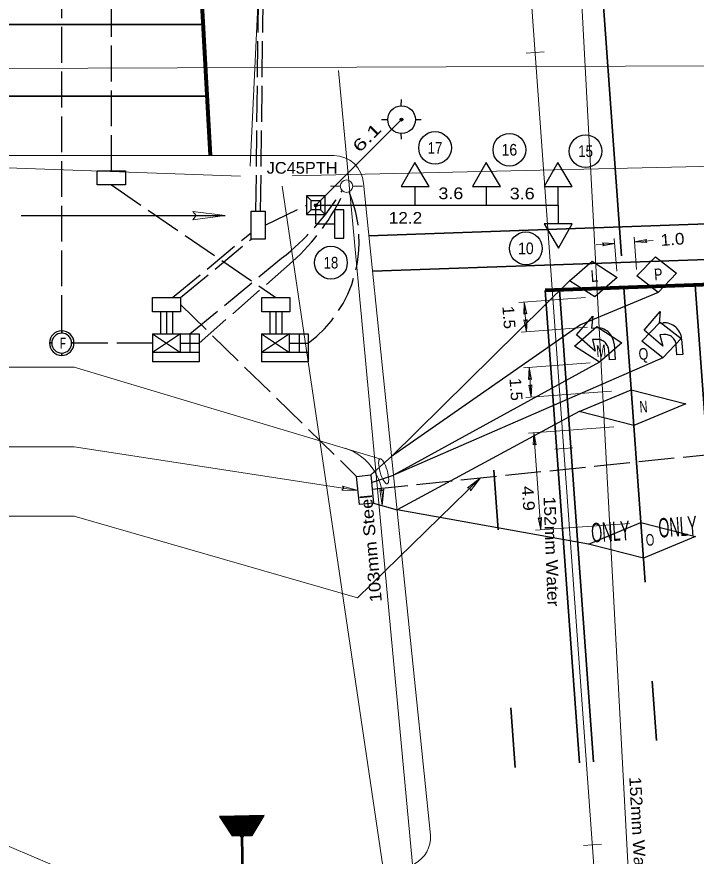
# Model space of a CAD drawing. Extents: x 168203 to 169864, y 223196 to 223870.
# Drawn here: x 168325.25 to 168359.48, y 223583.39 to 223625.66 of the extents above; entities that cross this region are included whole.
import ezdxf
from ezdxf.enums import TextEntityAlignment as Align

# ---------------------------------------------------------------- set-up
doc = ezdxf.new("R2010")
doc.units = 0
doc.header["$LTSCALE"] = 0.3
doc.header["$PDMODE"] = 32
doc.header["$PDSIZE"] = 0.15
doc.linetypes.add('LONG_DASH_SHORT_DASH', pattern=[9.9, 6, -1.2, 1.5, -1.2])
doc.linetypes.add('LONG_DASHED', pattern=[7.5, 6, -1.5])
for name, color, linetype, lineweight in [('1', 7, 'Continuous', 13), ('10', 7, 'Continuous', 13), ('23', 7, 'Continuous', 25), ('32', 7, 'Continuous', 25), ('36', 7, 'Continuous', 35), ('4', 7, 'Continuous', 25), ('6', 7, 'Continuous', 25), ('8', 7, 'Continuous', 25)]:
    doc.layers.add(name, color=color, linetype=linetype, lineweight=lineweight)

msp = doc.modelspace()

# ---------------------------------------------------------------- linework, layer by layer
at = {"layer": '1'}
for p, q in [((168355.9956, 223559.8648), (168350.6186, 223634.2675)), ((168350.9207, 223623.8346), (168351.8184, 223623.8995)), ((168298.0344, 223618.6676), (168341.2267, 223618.6675)), ((168341.5495, 223617.1291), (168341.0495, 223617.1291)), ((168342.1745, 223617.1291), (168342.6745, 223617.1291)), ((168342.7229, 223617.2756), (168346.0972, 223584.4572)), ((168352.3629, 223603.8867), (168353.2606, 223603.9516)), ((168280.5516, 223602.5453), (168328.4093, 223582.3863)), ((168353.8048, 223583.9354), (168354.7025, 223584.0002))]:
    msp.add_line(p, q, dxfattribs=at)
msp.add_circle((168341.862, 223617.1291), 0.3125, dxfattribs=at)
for centre, start, end in [((168341.2267, 223617.1675), 4.13349, 90.00005), ((168344.6012, 223584.3492), 297.10142, 4.13349)]:
    msp.add_arc(centre, 1.5, start, end, dxfattribs=at)
at = {"layer": '10', "lineweight": 25}
msp.add_line((168325.472, 223615.6542), (168335.7557, 223615.6542), dxfattribs=at)
at = {"layer": '10'}
for p, q in [((168328.1441, 223608.0135), (168297.9363, 223608.0135)), ((168343.5506, 223603.4058), (168328.1441, 223608.0135)), ((168328.1441, 223604.0135), (168297.9363, 223604.0135)), ((168342.4448, 223601.8094), (168328.1441, 223604.0135)), ((168328.1441, 223600.5135), (168297.9363, 223600.5135))]:
    msp.add_line(p, q, dxfattribs=at)
for points in [[(168334.1291, 223615.853), (168335.7557, 223615.6542), (168334.1291, 223615.4374), (168334.2919, 223615.6542)], [(168347.9575, 223601.9456), (168348.6085, 223602.4431), (168348.1028, 223601.797), (168348.0852, 223601.9314)], [(168341.6561, 223602.0315), (168342.4448, 223601.8094), (168341.6245, 223601.8262), (168341.7214, 223601.9209)], [(168343.744, 223601.8665), (168343.659, 223601.0515), (168343.5363, 223601.8628), (168343.6461, 223601.7833)]]:
    msp.add_lwpolyline(points, close=True, dxfattribs=at)
msp.add_lwpolyline([(168348.6085, 223602.4431), (168342.4242, 223596.3958), (168328.1441, 223600.5135)], dxfattribs=at)
msp.add_arc((168340.9894, 223601.3663), 2.6881, 353.27499, 72.67074, dxfattribs=at)
msp.add_ellipse((168343.7344, 223602.7761), major_axis=(-0.1838, 0.6297), ratio=0.276966, dxfattribs=at)
at = {"layer": '23', "lineweight": 13}
for p, q in [((168357.586, 223554.132), (168349.5897, 223703.4835)), ((168340.1403, 223682.8465), (168337.0072, 223618.1402)), ((168298.0362, 223622.959), (168427.4519, 223623.4301)), ((168347.1263, 223562.1814), (168341.4609, 223622.959)), ((168233.3078, 223621.2838), (168336.515, 223617.6326)), ((168339.1201, 223617.6451), (168427.4519, 223619.7026)), ((168348.0491, 223553.4435), (168338.6279, 223617.1375))]:
    msp.add_line(p, q, dxfattribs=at)
at = {"layer": '23'}
for p, q in [((168335.4735, 223585.375), (168337.6918, 223585.4203)), ((168335.4897, 223585.3503), (168337.6767, 223585.395)), ((168335.5057, 223585.3255), (168337.6615, 223585.3697)), ((168335.5219, 223585.3009), (168337.6465, 223585.3444)), ((168335.538, 223585.2762), (168337.6313, 223585.3191)), ((168335.5542, 223585.2515), (168337.6162, 223585.2937)), ((168335.5703, 223585.2269), (168337.6011, 223585.2684)), ((168335.5864, 223585.2022), (168337.586, 223585.2432)), ((168335.6025, 223585.1775), (168337.5709, 223585.2179)), ((168335.6188, 223585.1529), (168337.5558, 223585.1925)), ((168335.6348, 223585.1282), (168337.5407, 223585.1672)), ((168335.6509, 223585.1035), (168337.5256, 223585.1419)), ((168335.6671, 223585.0788), (168337.5104, 223585.1166)), ((168335.6832, 223585.0541), (168337.4953, 223585.0912)), ((168335.6994, 223585.0294), (168337.4802, 223585.0659)), ((168335.7155, 223585.0048), (168337.4651, 223585.0406)), ((168335.7316, 223584.9801), (168337.45, 223585.0153)), ((168335.7478, 223584.9554), (168337.435, 223584.99)), ((168335.7639, 223584.9308), (168337.4198, 223584.9646)), ((168335.78, 223584.9061), (168337.4047, 223584.9394)), ((168335.7961, 223584.8814), (168337.3895, 223584.9141)), ((168335.8123, 223584.8568), (168337.3745, 223584.8888)), ((168335.8284, 223584.8321), (168337.3593, 223584.8634)), ((168335.8446, 223584.8074), (168337.3442, 223584.8381)), ((168335.8606, 223584.7827), (168337.3291, 223584.8128)), ((168335.8769, 223584.758), (168337.3141, 223584.7875)), ((168335.893, 223584.7334), (168337.2989, 223584.7622)), ((168335.9091, 223584.7087), (168337.2838, 223584.7368)), ((168335.9252, 223584.684), (168337.2687, 223584.7115)), ((168335.9413, 223584.6594), (168337.2536, 223584.6862)), ((168335.9575, 223584.6347), (168337.2384, 223584.6609)), ((168335.9736, 223584.61), (168337.2233, 223584.6355)), ((168335.9897, 223584.5853), (168337.2083, 223584.6103)), ((168336.0059, 223584.5606), (168337.1932, 223584.585)), ((168336.0221, 223584.5359), (168337.178, 223584.5597)), ((168336.0381, 223584.5113), (168337.163, 223584.5343)), ((168336.0543, 223584.4866), (168337.1479, 223584.509)), ((168336.0705, 223584.4619), (168337.1327, 223584.4837)), ((168336.0866, 223584.4373), (168337.1175, 223584.4584))]:
    msp.add_line(p, q, dxfattribs=at)
at = {"layer": '23', "lineweight": 53}
msp.add_line((168336.8416, 223572.7261), (168336.6026, 223584.4228), dxfattribs=at)
at = {"layer": '23'}
msp.add_lwpolyline([(168336.1027, 223584.4126), (168337.1025, 223584.4331), (168337.7069, 223585.4457), (168335.4573, 223585.3996)], close=True, dxfattribs=at)
msp.add_point((168336.6026, 223584.4228), dxfattribs=at)
at = {"layer": '32'}
for p, q in [((168340.3237, 223616.1675), (168344.6371, 223620.4809)), ((168345.3237, 223616.1675), (168345.3237, 223617.1073)), ((168348.9237, 223616.1675), (168348.9237, 223617.1073)), ((168340.3237, 223615.2277), (168340.3237, 223616.1675)), ((168352.5237, 223616.1675), (168352.5237, 223615.2277)), ((168340.3237, 223615.2277), (168341.2635, 223615.2277))]:
    msp.add_line(p, q, dxfattribs=at)
for points in [[(168345.3056, 223618.3271), (168344.6189, 223617.1073), (168345.3237, 223617.1073), (168346.0285, 223617.1073)], [(168348.9056, 223618.3271), (168348.2189, 223617.1073), (168348.9237, 223617.1073), (168349.6285, 223617.1073)], [(168352.5056, 223618.3271), (168351.8189, 223617.1073), (168352.5237, 223617.1073), (168353.2285, 223617.1073)], [(168341.7333, 223614.5138), (168341.7333, 223615.9325), (168341.2635, 223615.9325), (168341.2635, 223614.5138)], [(168352.5418, 223614.0079), (168353.2285, 223615.2277), (168352.5237, 223615.2277), (168351.8189, 223615.2277)]]:
    msp.add_lwpolyline(points, close=True, dxfattribs=at)
msp.add_lwpolyline([(168340.3237, 223616.1675), (168352.5237, 223616.1675), (168352.5237, 223617.1073)], dxfattribs=at)
for centre in [(168346.3229, 223619.0571), (168350.0688, 223618.964), (168353.9078, 223618.8942), (168350.8998, 223614.0005), (168341.0797, 223613.279)]:
    msp.add_circle(centre, 0.8236, dxfattribs=at)
at = {"layer": '36', "lineweight": 80}
for p, q in [((168335.0149, 223618.6671), (168334.1789, 223633.9633)), ((168374.8667, 223612.7316), (168351.8768, 223611.872))]:
    msp.add_line(p, q, dxfattribs=at)
at = {"layer": '36'}
for p, q in [((168355.7208, 223613.6203), (168354.7732, 223626.7317)), ((168319.4575, 223625.267), (168334.6542, 223625.267)), ((168298.0351, 223621.6671), (168334.851, 223621.667)), ((168374.0279, 223615.7265), (168342.9941, 223614.6383)), ((168375.9373, 223613.9924), (168343.1786, 223612.8438)), ((168353.5949, 223588.0975), (168351.8768, 223611.872)), ((168354.3131, 223588.1493), (168352.5967, 223611.8989)), ((168356.9077, 223597.1964), (168355.8364, 223612.0201)), ((168361.075, 223589.4767), (168359.4361, 223612.1546)), ((168349.4984, 223599.8327), (168349.2822, 223602.8249)), ((168357.4843, 223589.2172), (168357.268, 223592.2094)), ((168350.3634, 223587.8639), (168350.1472, 223590.8561))]:
    msp.add_line(p, q, dxfattribs=at)
at = {"layer": '36', "linetype": 'LONG_DASH_SHORT_DASH', "lineweight": 25}
for points in [[(168354.4494, 223609.4175), (168354.2548, 223609.4034), (168354.3942, 223608.8268), (168353.4554, 223609.639), (168354.2676, 223610.5778), (168354.2126, 223609.9871), (168354.4072, 223610.0012)], [(168357.8515, 223609.6633), (168357.6569, 223609.6492), (168357.7963, 223609.0726), (168356.8575, 223609.8848), (168357.6697, 223610.8236), (168357.6147, 223610.2329), (168357.8093, 223610.247)], [(168358.7481, 223609.4347), (168358.8043, 223608.6565), (168358.5125, 223608.6354), (168358.4773, 223609.1218)], [(168355.346, 223609.1889), (168355.4022, 223608.4107), (168355.1104, 223608.3896), (168355.0752, 223608.876)]]:
    msp.add_lwpolyline(points, dxfattribs=at)
for centre, radius in [((168357.8725, 223609.3714), 0.8778), ((168354.4704, 223609.1256), 0.8778), ((168354.4915, 223608.8338), 0.5852), ((168357.8936, 223609.0796), 0.5852)]:
    msp.add_arc(centre, radius, 4.13419, 94.13419, dxfattribs=at)
at = {"layer": '4'}
for p, q in [((168339.8448, 223616.6374), (168340.0798, 223616.4024)), ((168340.7846, 223616.6374), (168340.5496, 223616.4024)), ((168339.8448, 223615.6976), (168340.0798, 223615.9326)), ((168340.7846, 223615.6976), (168340.5496, 223615.9326))]:
    msp.add_line(p, q, dxfattribs=at)
for points in [[(168339.8448, 223616.6374), (168339.8448, 223615.6976), (168340.7846, 223615.6976), (168340.7846, 223616.6374)], [(168340.0798, 223616.4024), (168340.5496, 223616.4024), (168340.5496, 223615.9326), (168340.0798, 223615.9326)]]:
    msp.add_lwpolyline(points, close=True, dxfattribs=at)
msp.add_point((168340.3237, 223616.1675), dxfattribs=at)
at = {"layer": '6', "linetype": 'LONG_DASHED'}
for p, q in [((168337.299, 223615.8769), (168337.8409, 223661.006)), ((168337.5361, 223615.8769), (168338.0771, 223660.9241)), ((168327.5151, 223609.8472), (168327.5152, 223654.5336)), ((168330.0164, 223617.906), (168330.0165, 223654.3633)), ((168330.0164, 223617.1922), (168338.2986, 223611.5244)), ((168337.7676, 223615.1676), (168339.8448, 223616.1675)), ((168333.1047, 223611.5244), (168337.0538, 223614.7891)), ((168333.505, 223611.5244), (168337.0538, 223614.4582)), ((168333.9743, 223609.6986), (168338.5949, 223613.5)), ((168334.4352, 223609.2287), (168339.1426, 223613.3344)), ((168333.505, 223611.1675), (168342.3722, 223602.515)), ((168332.5, 223610.8106), (168332.5, 223609.6986)), ((168332.7956, 223610.8106), (168332.7956, 223609.6986)), ((168333.0994, 223610.8106), (168333.0994, 223609.6986)), ((168338.003, 223610.8106), (168338.003, 223609.6986)), ((168338.2986, 223610.8106), (168338.2986, 223609.6986)), ((168338.6024, 223610.8106), (168338.6024, 223609.6986)), ((168332.0858, 223609.2287), (168328.1336, 223609.2287)), ((168343.1548, 223601.8824), (168372.8225, 223604.9326)), ((168343.0823, 223602.588), (168344.137, 223603.5217)), ((168343.1206, 223602.2151), (168344.2347, 223602.5721)), ((168343.2274, 223601.1767), (168344.4135, 223600.8327))]:
    msp.add_line(p, q, dxfattribs=at)
at = {"layer": '6', "lineweight": 13}
for p, q in [((168355.4744, 223612.8592), (168355.3562, 223614.4939)), ((168356.4725, 223612.9314), (168356.3543, 223614.5661)), ((168356.3721, 223614.3203), (168357.3101, 223614.3881)), ((168354.436, 223614.1804), (168355.374, 223614.2482)), ((168350.5485, 223611.2783), (168353.8961, 223611.5202)), ((168350.9293, 223609.8018), (168350.8212, 223611.2979)), ((168350.6566, 223609.7822), (168354.0042, 223610.0241)), ((168350.7863, 223607.9868), (168354.1339, 223608.2287)), ((168351.1671, 223606.5103), (168351.059, 223608.0065)), ((168350.8944, 223606.4906), (168355.2071, 223606.8023)), ((168351.0242, 223604.6952), (168355.3369, 223605.0069)), ((168351.6501, 223599.8276), (168351.2969, 223604.7149)), ((168351.3774, 223599.8079), (168356.1187, 223600.1506))]:
    msp.add_line(p, q, dxfattribs=at)
at = {"layer": '6'}
for p, q in [((168353.1038, 223612.3653), (168344.137, 223603.5217)), ((168327.5151, 223609.8488), (168327.5151, 223609.7313)), ((168327.5151, 223609.7313), (168327.5151, 223609.8488)), ((168327.5151, 223609.7313), (168327.5151, 223609.8488)), ((168327.5151, 223609.7313), (168327.5151, 223609.8488)), ((168332.0858, 223609.6986), (168333.4954, 223608.7588)), ((168333.4954, 223609.6986), (168332.0858, 223608.7588)), ((168332.0858, 223609.6986), (168334.4352, 223609.6986)), ((168332.0858, 223609.6986), (168332.0858, 223608.7588)), ((168333.4954, 223608.7588), (168333.4954, 223609.6986)), ((168333.9743, 223609.6986), (168333.9743, 223608.7588)), ((168334.4352, 223609.6986), (168334.4352, 223608.7588)), ((168337.5888, 223609.6986), (168338.9984, 223608.7588)), ((168338.9984, 223609.6986), (168337.5888, 223608.7588)), ((168337.5888, 223609.6986), (168339.9382, 223609.6986)), ((168337.5888, 223609.6986), (168337.5888, 223608.7588)), ((168338.9984, 223608.7588), (168338.9984, 223609.6986)), ((168339.4773, 223609.6986), (168339.4773, 223608.7588)), ((168339.9382, 223609.6986), (168339.9382, 223608.7588)), ((168327.0181, 223609.2343), (168326.8916, 223609.2343)), ((168326.8916, 223609.2343), (168327.0181, 223609.2343)), ((168326.8916, 223609.2343), (168327.0181, 223609.2343)), ((168327.0181, 223609.2343), (168326.8916, 223609.2343)), ((168328.0121, 223609.2343), (168328.1386, 223609.2343)), ((168328.1386, 223609.2343), (168328.0121, 223609.2343)), ((168328.0121, 223609.2343), (168328.1386, 223609.2343)), ((168328.1386, 223609.2343), (168328.0121, 223609.2343)), ((168333.4954, 223609.2287), (168334.4352, 223609.2287)), ((168338.9984, 223609.2287), (168339.9382, 223609.2287)), ((168327.5151, 223608.6108), (168327.5151, 223608.7283)), ((168327.5151, 223608.7283), (168327.5151, 223608.6108)), ((168327.5151, 223608.6108), (168327.5151, 223608.7283)), ((168327.5151, 223608.6108), (168327.5151, 223608.7283)), ((168334.4352, 223608.7588), (168332.0858, 223608.7588)), ((168332.0858, 223608.7588), (168332.0858, 223608.2889)), ((168334.4352, 223608.7588), (168334.4352, 223608.2889)), ((168339.9382, 223608.7588), (168337.5888, 223608.7588)), ((168337.5888, 223608.7588), (168337.5888, 223608.2889)), ((168339.9382, 223608.7588), (168339.9382, 223608.2889)), ((168357.7959, 223608.4933), (168344.2347, 223602.5721)), ((168334.4352, 223608.2889), (168332.0858, 223608.2889)), ((168339.9382, 223608.2889), (168337.5888, 223608.2889)), ((168354.6035, 223608.2625), (168344.2347, 223602.5721)), ((168353.5796, 223605.7823), (168344.4135, 223600.8327)), ((168354.0626, 223599.0996), (168344.4135, 223600.8327))]:
    msp.add_line(p, q, dxfattribs=at)
for points in [[(168329.3071, 223617.1922), (168329.3071, 223617.906), (168330.7258, 223617.906), (168330.7258, 223617.1922)], [(168337.7676, 223614.4582), (168337.0538, 223614.4582), (168337.0538, 223615.8769), (168337.7676, 223615.8769)], [(168356.4957, 223612.6104), (168357.4282, 223613.5802), (168358.4904, 223612.7546), (168357.558, 223611.7848)], [(168354.2359, 223613.3495), (168355.4976, 223612.5383), (168354.3656, 223611.5541), (168353.1038, 223612.3653)], [(168332.0863, 223610.8106), (168332.0863, 223611.5244), (168333.505, 223611.5244), (168333.505, 223610.8106)], [(168337.5893, 223610.8106), (168337.5893, 223611.5244), (168339.008, 223611.5244), (168339.008, 223610.8106)], [(168356.7336, 223609.3189), (168357.6661, 223610.2887), (168358.7283, 223609.4631), (168357.7959, 223608.4933)], [(168354.4738, 223610.0579), (168355.7355, 223609.2467), (168354.6035, 223608.2625), (168353.3417, 223609.0737)], [(168353.5796, 223605.7823), (168356.208, 223606.8746), (168358.9662, 223606.1716), (168356.3378, 223605.0792)], [(168342.3722, 223602.515), (168343.0823, 223602.588), (168343.2274, 223601.1767), (168342.5173, 223601.1037)], [(168354.0626, 223599.0996), (168356.691, 223600.1919), (168359.4492, 223599.4889), (168356.8208, 223598.3965)]]:
    msp.add_lwpolyline(points, close=True, dxfattribs=at)
at = {"layer": '6', "lineweight": 13}
for points in [[(168356.9858, 223614.2899), (168356.3721, 223614.3203), (168356.9746, 223614.4453), (168356.9196, 223614.3598)], [(168354.7603, 223614.2786), (168355.374, 223614.2482), (168354.7715, 223614.1232), (168354.8265, 223614.2087)], [(168350.7908, 223610.6842), (168350.8212, 223611.2979), (168350.9462, 223610.6954), (168350.8607, 223610.7504)], [(168350.9597, 223610.4155), (168350.9293, 223609.8018), (168350.8043, 223610.4043), (168350.8898, 223610.3493)], [(168351.0286, 223607.3928), (168351.059, 223608.0065), (168351.184, 223607.404), (168351.0985, 223607.459)], [(168351.1975, 223607.124), (168351.1671, 223606.5103), (168351.0421, 223607.1128), (168351.1276, 223607.0578)], [(168351.2665, 223604.1012), (168351.2969, 223604.7149), (168351.4219, 223604.1124), (168351.3364, 223604.1674)], [(168351.6805, 223600.4413), (168351.6501, 223599.8276), (168351.5251, 223600.4301), (168351.6106, 223600.3751)]]:
    msp.add_lwpolyline(points, close=True, dxfattribs=at)
at = {"layer": '6'}
msp.add_lwpolyline([(168357.558, 223611.7848), (168353.6504, 223610.157), (168344.137, 223603.5217)], dxfattribs=at)
at = {"layer": '6', "linetype": 'LONG_DASHED'}
for centre, radius, start, end in [((168330.2654, 223624.0427), 13.4361, 308.31148, 327.89744), ((168331.9487, 223621.3616), 10.779, 311.86635, 335.21891), ((168336.1096, 223614.3454), 6.3906, 306.80597, 23.02086)]:
    msp.add_arc(centre, radius, start, end, dxfattribs=at)
at = {"layer": '6'}
for radius, start, end in [(0.6185, 90, 180), (0.6185, 90, 180), (0.5005, 90, 180), (0.5005, 90, 180), (0.6185, 0, 90), (0.6185, 0, 90), (0.5005, 0, 90), (0.5005, 0, 90), (0.6185, 180, 270), (0.6185, 180, 270), (0.5005, 180, 270), (0.5005, 180, 270), (0.5005, 270, 0), (0.6185, 270, 0), (0.5005, 270, 0), (0.6185, 270, 0)]:
    msp.add_arc((168327.5151, 223609.2287), radius, start, end, dxfattribs=at)
at = {"layer": '8'}
for p, q in [((168344.6211, 223621.1741), (168344.6275, 223621.4873)), ((168343.6243, 223620.4841), (168343.9438, 223620.4841)), ((168345.3368, 223620.4841), (168345.6242, 223620.4905)), ((168344.6275, 223619.4938), (168344.6211, 223619.7813))]:
    msp.add_line(p, q, dxfattribs=at)
msp.add_circle((168344.6371, 223620.4809), 0.6965, dxfattribs=at)
msp.add_point((168344.6339, 223620.4841), dxfattribs=at)

# ---------------------------------------------------------------- texts
at = {"layer": '1', "width": 1.05}
msp.add_text('JC45PTH', height=0.5873, dxfattribs=at).set_placement((168339.6286, 223617.7594), align=Align.CENTER)
at = {"layer": '23'}
for s, rotation, width, p in [('103mm Steel', 95.325, 1.15, (168343.3953, 223598.9155)), ('152mm Water', 272.144, 1.1, (168351.8933, 223598.7263)), ('152mm Water', 273.065, 1.1, (168356.2546, 223584.6096))]:
    msp.add_text(s, height=0.6, rotation=rotation, dxfattribs=dict(at, width=width)).set_placement(p, align=Align.CENTER)
at = {"layer": '32', "width": 1.5}
msp.add_text('6.1', height=0.5873, rotation=45, dxfattribs=at).set_placement((168343.0984, 223619.3665), align=Align.CENTER)
at = {"layer": '32'}
for s, width, p in [('17', 0.85, (168346.3228, 223618.7635)), ('16', 0.9, (168350.0688, 223618.6704)), ('15', 0.85, (168353.9078, 223618.6006)), ('3.6', 1.15, (168347.1205, 223616.4771)), ('3.6', 1.15, (168350.7153, 223616.4675)), ('12.2', 1.1, (168344.8363, 223615.2411)), ('10', 0.9, (168350.8998, 223613.7069)), ('18', 0.85, (168341.0796, 223612.9854))]:
    msp.add_text(s, height=0.5873, dxfattribs=dict(at, width=width)).set_placement(p, align=Align.CENTER)
at = {"layer": '36', "width": 0.55}
for p in [(168358.5823, 223599.4982), (168355.1935, 223599.2539)]:
    msp.add_text('ONLY', height=0.9715, rotation=3.898, dxfattribs=at).set_placement(p, align=Align.CENTER)
at = {"layer": '6'}
for s, rotation, width, p in [('1.0', 4.132, 1.1, (168358.3089, 223614.1625)), ('L', 4.134, 0.85, (168354.3719, 223612.3153)), ('P', 4.134, 0.8, (168357.5919, 223612.4003)), ('1.5', 274.133, 1.05, (168349.7562, 223610.5004)), ('M', 4.134, 0.75, (168354.7115, 223608.5469)), ('Q', 4.134, 0.8, (168356.8431, 223608.3925)), ('1.5', 274.132, 1.05, (168350.1129, 223606.8792)), ('N', 4.134, 0.7, (168356.8463, 223605.7326)), ('4.9', 274.134, 1.15, (168350.7326, 223601.391)), ('O', 4.134, 0.7, (168357.1773, 223599.032))]:
    msp.add_text(s, height=0.5873, rotation=rotation, dxfattribs=dict(at, width=width)).set_placement(p, align=Align.CENTER)
at = {"layer": '6', "width": 0.7}
msp.add_text('F', height=0.5506, dxfattribs=at).set_placement((168327.4157, 223608.9452))

doc.saveas('drawing.dxf')
